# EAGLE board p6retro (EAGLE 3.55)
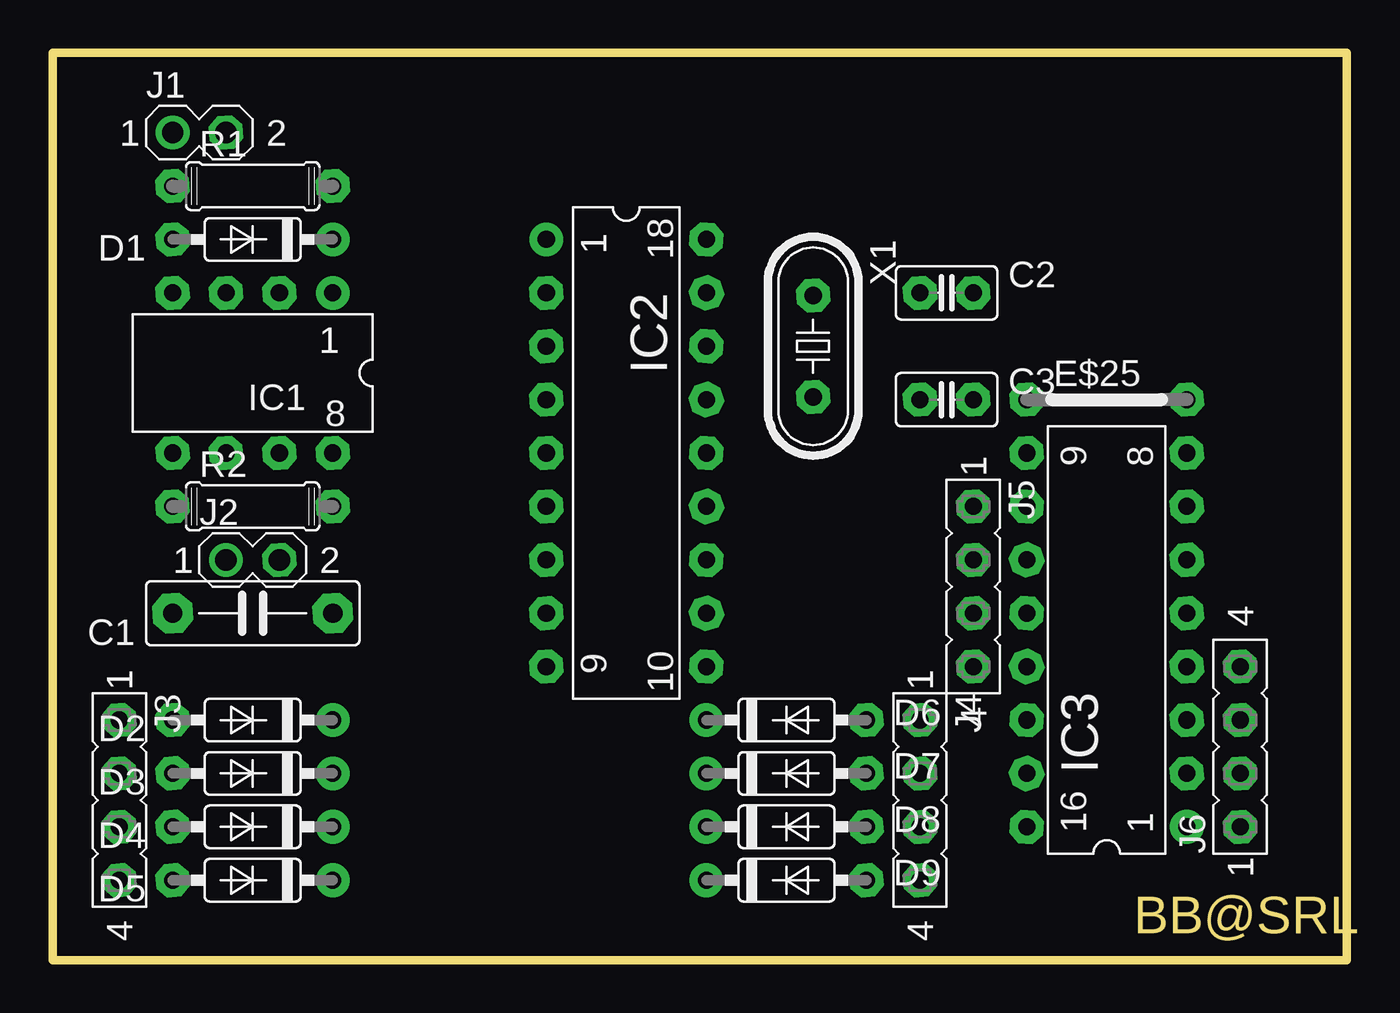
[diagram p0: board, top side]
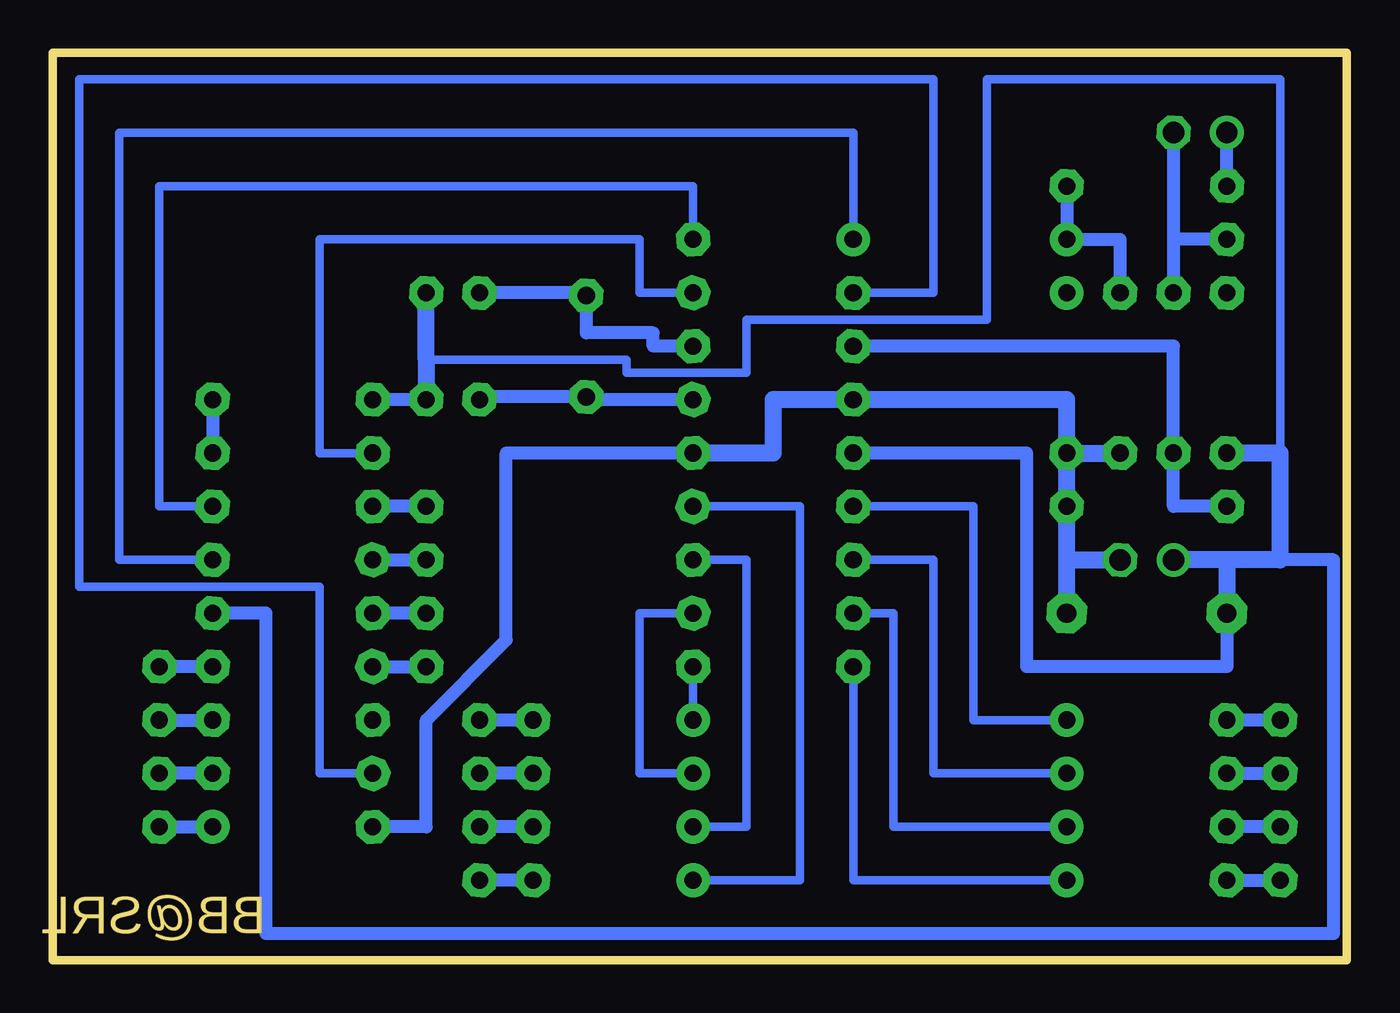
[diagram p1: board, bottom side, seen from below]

Size 61.59 x 43.18 mm. Coordinates in mm from the lower left corner, seen from the top.
Outline: 0,43.18 61.59,43.18 61.59,0 0,0 0,43.18
Copper layers used: Bottom

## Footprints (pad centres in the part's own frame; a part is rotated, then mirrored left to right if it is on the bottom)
,5B3 = drill 0.914 pad 1.905 octagon:  -3.81,0;  3.81,0
,5-2 = drill 0.813 pad 1.6 octagon:  -1.27,0;  1.27,0
35-7 = drill 0.813 pad 1.6 round:  -3.81,0 | drill 0.813 pad 1.6 octagon:  3.81,0
 = drill 0.813 pad 1.6 octagon:  -3.81,0;  3.81,0
L08 = drill 0.813 pad 1.6 round:  -3.81,-3.81 | drill 0.813 pad 1.6 octagon:  -1.27,-3.81;  1.27,-3.81;  3.81,-3.81;  3.81,3.81;  1.27,3.81;  -1.27,3.81;  -3.81,3.81
L18 = drill 0.813 pad 1.6 round:  -10.16,-3.81 | drill 0.813 pad 1.6 octagon:  -7.62,-3.81;  -5.08,-3.81;  -2.54,-3.81;  0,-3.81;  2.54,-3.81;  5.08,-3.81;  7.62,-3.81;  10.16,-3.81;  10.16,3.81;  7.62,3.81;  5.08,3.81;  2.54,3.81;  0,3.81;  -2.54,3.81;  -5.08,3.81;  -7.62,3.81;  -10.16,3.81
L16 = drill 0.813 pad 1.6 round:  -8.89,-3.81 | drill 0.813 pad 1.6 octagon:  -6.35,-3.81;  -3.81,-3.81;  -1.27,-3.81;  1.27,-3.81;  3.81,-3.81;  6.35,-3.81;  8.89,-3.81;  8.89,3.81;  6.35,3.81;  3.81,3.81;  1.27,3.81;  -1.27,3.81;  -3.81,3.81;  -6.35,3.81;  -8.89,3.81
02-1 = drill 1.016 pad 1.6 round:  -1.27,0 | drill 1.016 pad 1.6 octagon:  1.27,0
04-1 = drill 0.813 pad 1.6 octagon:  -3.81,0;  -1.27,0;  1.27,0;  3.81,0
07/7 = drill 0.813 pad 1.6 octagon:  -3.81,0;  3.81,0
49/S = drill 0.813 pad 1.6 octagon:  -2.413,0;  2.413,0

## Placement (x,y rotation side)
C1  0.1  [,5B3]  9.53,16.51 180 top
C2  33p  [,5-2]  42.54,31.75 0 top
C3  33p  [,5-2]  42.54,26.67 0 top
D1  1N4148  [35-7]  9.53,34.29 180 top
D2  1N4148  [35-7]  9.53,11.43 180 top
D3  1N4148  [35-7]  9.53,8.89 180 top
D4  1N4148  [35-7]  9.53,6.35 180 top
D5  1N4148  [35-7]  9.53,3.81 180 top
D6  1N4148  [35-7]  34.92,11.43 0 top
D7  1N4148  [35-7]  34.92,8.89 0 top
D8  1N4148  [35-7]  34.92,6.35 0 top
D9  1N4148  [35-7]  34.92,3.81 0 top
E$25  []  50.16,26.67 0 top
IC1  6N137  [L08]  9.53,27.94 180 top
IC2  PIC16F84/10MHz  [L18]  27.3,24.13 270 top
IC3  74HC148  [L16]  50.16,15.24 90 top
J1  [02-1]  6.98,39.37 0 top
J2  [02-1]  9.53,19.05 0 top
J3  [04-1]  3.17,7.62 270 top
J4  [04-1]  41.27,7.62 270 top
J5  [04-1]  43.81,17.78 270 top
J6  [04-1]  56.51,10.16 90 top
R1  220  [07/7]  9.53,36.83 0 top
R2  360  [07/7]  9.53,21.59 0 top
X1  8MHz  [49/S]  36.2,29.21 270 top

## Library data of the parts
C1-C3 = cap
D1-D9 = diode
E$25 = JUMPER
IC1 = optocpl
IC2 = pic
IC3 = 40XX
J1 J2 = CON-LSTB
J3-J6 = con-lsta
R1 R2 = r
X1 = quartz

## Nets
S$1: IC1. IC2. R2.
S$2: C1. IC1. IC2. IC3. J2. R2.
S$3: D3. IC2.
S$4: C3. IC2. X1.
S$5: D1. IC1. R1.
S$6: D6. IC2.
S$7: D8. IC2.
S$8: D9. IC2.
S$9: D6. J4.
S$10: D5. IC2.
S$11: D4. IC2.
S$12: D7. J4.
S$13: D8. J4.
S$14: D9. J4.
S$15: D5. J3.
S$16: D2. IC2.
S$17: C2. IC2. X1.
S$18: C1. C2. C3. E$25. IC1. IC2. IC3. J2.
S$19: J1. R1.
S$20: D4. J3.
S$21: D1. IC1. J1.
S$22: IC2. IC3.
S$23: IC2. IC3.
S$24: IC2. IC3.
S$25: IC2. IC3.
S$26: D3. J3.
S$27: D2. J3.
S$28: IC3. J5.
S$29: IC3. J5.
S$30: IC3. J5.
S$31: IC3. J5.
S$32: IC3. J6.
S$33: IC3. J6.
S$34: IC3. J6.
S$35: IC3. J6.
S$36: D7. IC2.
S$37: E$25. IC3.

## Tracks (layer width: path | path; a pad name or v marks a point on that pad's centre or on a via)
S$1
  Bottom 0.61: 5.71,21.59 8.26,21.59 8.26,24.13 8.26,29.21 23.49,29.21
S$2
  Bottom 0.61: 31.11,24.13 40,24.13 40,15.24 43.81,11.43 43.81,6.35 IC3.
  Bottom 0.813: IC1. 10.79,24.13 | IC1. R2. 13.33,19.05 | 13.33,19.05 J2. | 13.33,16.51 13.33,19.05 | IC1. 13.33,26.67 23.49,26.67 27.3,26.67 27.3,24.13 31.11,24.13
S$3
  Bottom 0.406: 23.49,19.05 19.69,19.05 19.69,8.89 13.33,8.89
S$4
  Bottom 0.406: 36.2,26.67 X1. | 41.27,26.8 41.27,26.67
  Bottom 0.61: 31.11,26.67 36.2,26.67 | X1. 41.27,26.8
S$5
  Bottom 0.61: 10.79,31.75 10.79,34.29 13.33,34.29 R1.
S$6
  Bottom 0.406: 31.11,11.43 31.11,13.97
S$7
  Bottom 0.406: 31.11,19.05 28.57,19.05 28.57,6.35 31.11,6.35
S$8
  Bottom 0.406: 31.11,21.59 26.03,21.59 26.03,3.81 31.11,3.81
S$9
  Bottom 0.61: D6. 41.27,11.43
S$10
  Bottom 0.406: 13.33,3.81 23.49,3.81 23.49,13.97
S$11
  Bottom 0.406: 23.49,16.51 21.59,16.51 21.59,6.35 13.33,6.35
S$12
  Bottom 0.61: D7. 41.27,8.89
S$13
  Bottom 0.61: D8. 41.27,6.35
S$14
  Bottom 0.61: D9. J4.
S$15
  Bottom 0.61: D5. J3.
S$16
  Bottom 0.406: 23.49,21.59 17.78,21.59 17.78,11.43 13.33,11.43
S$17
  Bottom 0.406: 36.2,31.62 36.2,31.75
  Bottom 0.61: 36.2,31.75 41.27,31.75 | 36.2,31.62 36.2,29.85 33.02,29.85 33.02,29.21 31.11,29.21
S$18
  Bottom 0.406: 43.81,28.58 34.29,28.58 34.29,27.94 28.57,27.94 28.57,30.48 17.14,30.48 17.14,41.91 3.17,41.91 3.17,24.13
  Bottom 0.61: 23.49,24.13 15.24,24.13 15.24,13.97 5.71,13.97 C1. | 53.97,16.51 51.43,16.51 51.43,1.27 0.63,1.27 0.63,19.05 3.17,19.05 | C3. 46.35,26.67
  Bottom 0.813: C3. 43.81,28.58 C2. | 5.71,19.05 8.26,19.05 | 5.71,19.05 C1. | 5.71,24.13 3.17,24.13 3.17,19.05 5.71,19.05
S$19
  Bottom 0.61: 5.71,36.83 5.71,39.37
S$20
  Bottom 0.61: 3.17,6.35 D4.
S$21
  Bottom 0.61: 8.26,34.29 8.26,31.75 | D1. 8.26,34.29 | J1. 8.26,34.29
S$22
  Bottom 0.406: 46.35,8.89 48.89,8.89 48.89,17.78 60.32,17.78 60.32,41.91 19.69,41.91 19.69,31.75 23.49,31.75
S$23
  Bottom 0.406: 53.97,19.05 58.42,19.05 58.42,39.37 23.49,39.37 23.49,34.29
S$24
  Bottom 0.406: IC2. 31.11,36.83 56.51,36.83 56.51,21.59 53.97,21.59
S$25
  Bottom 0.406: 31.11,31.75 33.65,31.75 33.65,34.29 48.89,34.29 48.89,24.13 46.35,24.13
S$26
  Bottom 0.61: D3. 3.17,8.89
S$27
  Bottom 0.61: 3.17,11.43 D2.
S$28
  Bottom 0.61: 43.81,21.59 46.35,21.59
S$29
  Bottom 0.61: 46.35,19.05 43.81,19.05
S$30
  Bottom 0.61: 43.81,16.51 46.35,16.51
S$31
  Bottom 0.61: 46.35,13.97 J5.
S$32
  Bottom 0.61: 56.51,6.35 53.97,6.35
S$33
  Bottom 0.61: 53.97,8.89 56.51,8.89
S$34
  Bottom 0.61: 56.51,11.43 53.97,11.43
S$35
  Bottom 0.61: 53.97,13.97 J6.
S$36
  Bottom 0.406: 31.11,16.51 33.65,16.51 33.65,8.89 31.11,8.89
S$37
  Bottom 0.61: E$25. 53.97,24.13

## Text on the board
Dimension: BB@SRL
